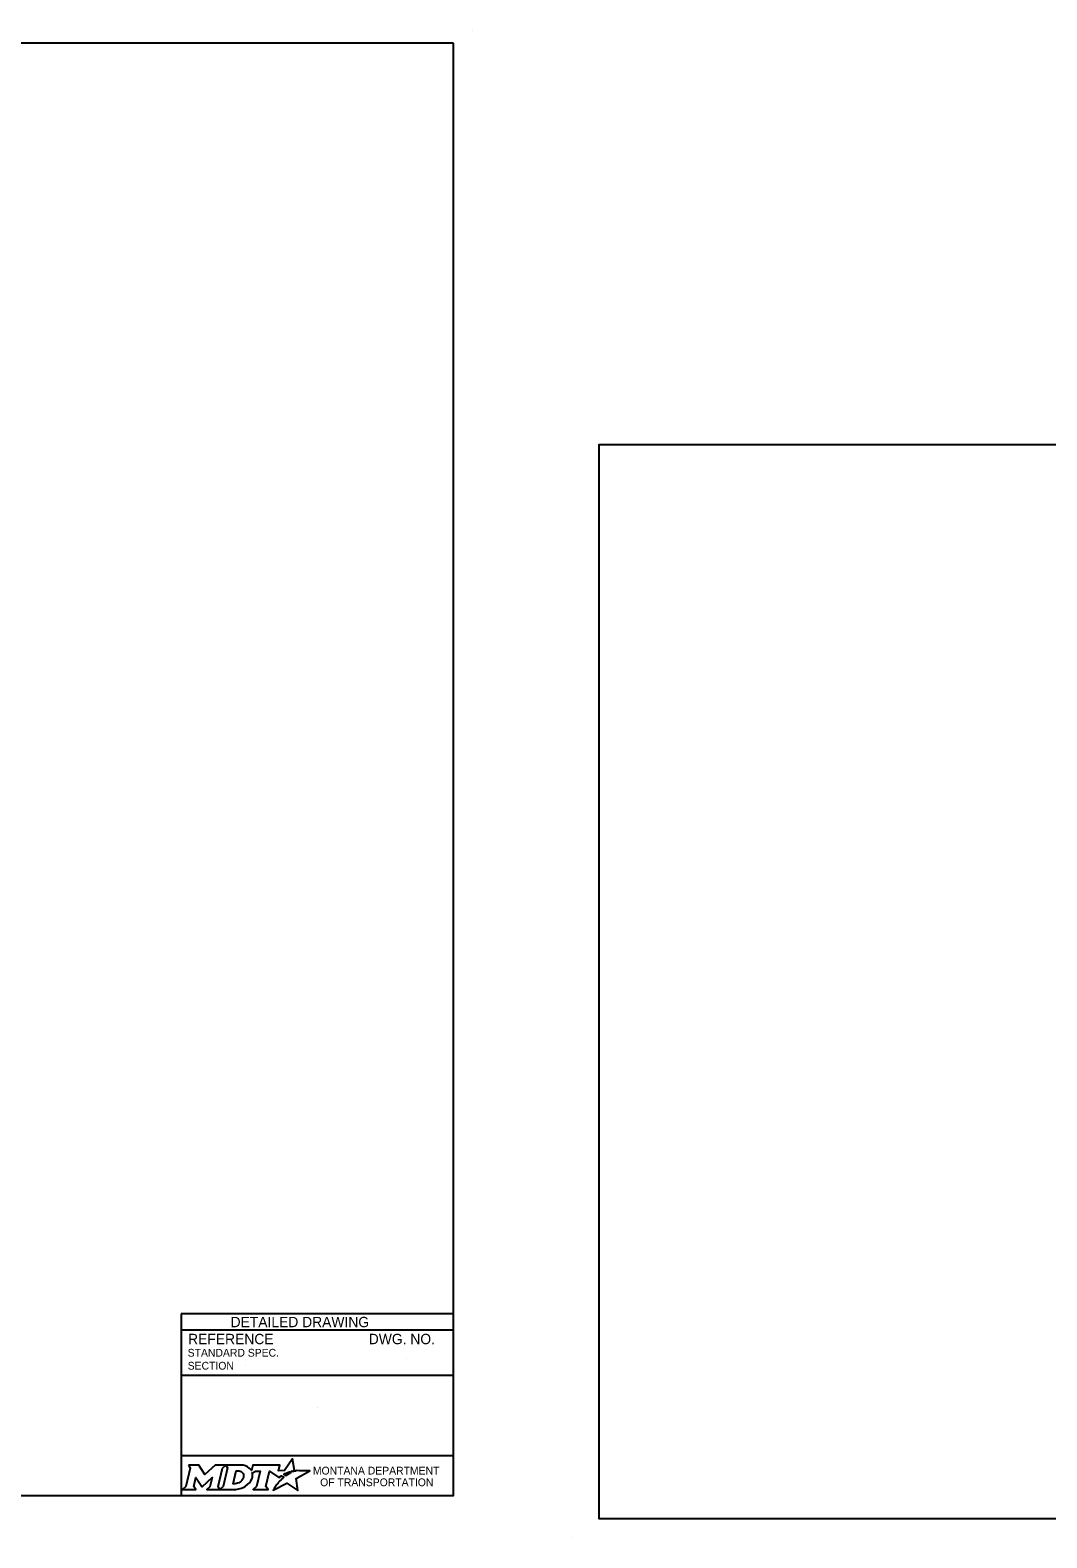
# Model space of a CAD drawing. Extents: x 49991.4 to 50061.4, y 49960.6 to 50011.4.
# Drawn here: x 50005.35 to 50013.19, y 49999.74 to 50011.36 of the extents above; entities that cross this region are included whole.
import ezdxf

# ---------------------------------------------------------------- set-up
doc = ezdxf.new("R2010")
doc.units = 0
doc.layers.add('Level 1', color=7, linetype='Continuous')
doc.layers.add('Level 2', color=7, linetype='Continuous')

msp = doc.modelspace()

# ---------------------------------------------------------------- linework, layer by layer
at = {"layer": 'Level 1'}
for p, q in [((50008.765, 50011.363), (50008.765, 50011.363)), ((50009.537, 49999.736), (50009.537, 49999.736))]:
    msp.add_line(p, q, dxfattribs=at)
for points in [[(50008.615, 50011.263), (50000.336, 50011.263), (50000.336, 50000.062), (50008.615, 50000.062)], [(50020.938, 50008.165), (50009.737, 50008.165), (50009.737, 49999.886), (50020.938, 49999.886)]]:
    msp.add_lwpolyline(points, close=True, dxfattribs=at)
at = {"layer": 'Level 2'}
for p, q in [((50008.615, 50001.462), (50006.515, 50001.462)), ((50006.515, 50001.462), (50006.515, 50000.062)), ((50008.615, 50001.337), (50006.515, 50001.337)), ((50007.009, 50001.063), (50007.009, 50001.063)), ((50008.251, 50001.122), (50008.251, 50001.122)), ((50008.615, 50000.987), (50006.515, 50000.987)), ((50007.565, 50000.738), (50007.565, 50000.738)), ((50008.615, 50000.369), (50006.515, 50000.369))]:
    msp.add_line(p, q, dxfattribs=at)
for points in [[(50007.377, 50000.245), (50007.367, 50000.25), (50007.378, 50000.253), (50007.39, 50000.255), (50007.373, 50000.345), (50007.313, 50000.254), (50007.266, 50000.253), (50007.276, 50000.297), (50007.067, 50000.297), (50007.057, 50000.255), (50007.051, 50000.263)], [(50006.57, 50000.297), (50006.584, 50000.274), (50006.551, 50000.131), (50006.525, 50000.108), (50006.627, 50000.108), (50006.613, 50000.131), (50006.629, 50000.201), (50006.673, 50000.132), (50006.678, 50000.132), (50006.753, 50000.202), (50006.737, 50000.13), (50006.712, 50000.108), (50006.814, 50000.108), (50006.8, 50000.132), (50006.833, 50000.274)], [(50006.833, 50000.274), (50006.859, 50000.297), (50006.776, 50000.297), (50006.697, 50000.224), (50006.652, 50000.297), (50006.57, 50000.297)], [(50006.972, 50000.297), (50006.859, 50000.297), (50006.873, 50000.275), (50006.839, 50000.131), (50006.814, 50000.108), (50006.925, 50000.108)], [(50006.996, 50000.211), (50006.995, 50000.203), (50006.992, 50000.193), (50006.988, 50000.185), (50006.982, 50000.178), (50006.976, 50000.171), (50006.968, 50000.164), (50006.959, 50000.16), (50006.95, 50000.156), (50006.941, 50000.154), (50006.932, 50000.153), (50006.916, 50000.153), (50006.94, 50000.253), (50006.956, 50000.253), (50006.963, 50000.252), (50006.971, 50000.25), (50006.977, 50000.247), (50006.983, 50000.243), (50006.988, 50000.238), (50006.992, 50000.232), (50006.995, 50000.226), (50006.996, 50000.218), (50006.996, 50000.215), (50006.996, 50000.211)], [(50007.064, 50000.238), (50007.088, 50000.251), (50007.125, 50000.251), (50007.097, 50000.131), (50007.069, 50000.108), (50007.185, 50000.108), (50007.168, 50000.131), (50007.196, 50000.251), (50007.268, 50000.2), (50007.289, 50000.215), (50007.309, 50000.204)], [(50007.253, 50000.148), (50007.237, 50000.124), (50007.233, 50000.116), (50007.227, 50000.107), (50007.225, 50000.103), (50007.33, 50000.156), (50007.414, 50000.101), (50007.401, 50000.194), (50007.508, 50000.252), (50007.458, 50000.253), (50007.428, 50000.253), (50007.407, 50000.254), (50007.401, 50000.252), (50007.396, 50000.251), (50007.387, 50000.249), (50007.377, 50000.245)], [(50007.327, 50000.217), (50007.324, 50000.215), (50007.306, 50000.225), (50007.316, 50000.231), (50007.32, 50000.233), (50007.329, 50000.237), (50007.335, 50000.239), (50007.343, 50000.243), (50007.35, 50000.245), (50007.362, 50000.238), (50007.358, 50000.236), (50007.353, 50000.233), (50007.349, 50000.231), (50007.344, 50000.228), (50007.342, 50000.227), (50007.339, 50000.225), (50007.337, 50000.224), (50007.334, 50000.222), (50007.332, 50000.221), (50007.329, 50000.219), (50007.327, 50000.217)], [(50006.97, 50000.116), (50006.979, 50000.118), (50006.992, 50000.124), (50007.012, 50000.135)], [(50007.267, 50000.164), (50007.267, 50000.164)]]:
    msp.add_lwpolyline(points, dxfattribs=at)
for centre, radius, start, end in [((50006.995, 50000.219), 0.0709, 339.5329, 15.8582), ((50006.951, 50000.236), 0.118, 300.9103, 339.1383)]:
    msp.add_arc(centre, radius, start, end, dxfattribs=at)
for centre, major_axis, ratio, start_param, end_param in [((50006.97, 50000.25), (0.0834, -0.0037), 0.568097, 0.61298, 1.570796), ((50007.026, 50000.257), (0.0361, -0.0295), 0.469099, 1.225588, 1.570796), ((50006.925, 50000.257), (0, 0.148), 0.987302, 3.139398, 3.456847), ((50007.26, 50000.156), (-0.00694, -0.00806), 0.008222, 0, 3.137361), ((50007.276, 50000.174), (-0.0098, -0.0102), 0.016458, 3.141593, 6.279097), ((50007.297, 50000.194), (-0.0112, -0.0097), 0.021651, 3.157348, 6.283185)]:
    msp.add_ellipse(centre, major_axis=major_axis, ratio=ratio, start_param=start_param, end_param=end_param, dxfattribs=at)

# ---------------------------------------------------------------- texts
for s, height, p in [('DETAILED DRAWING', 0.0799, (50006.896, 50001.36)), ('REFERENCE', 0.08, (50006.568, 50001.229)), ('DWG. NO.', 0.08, (50007.962, 50001.229)), ('STANDARD SPEC.', 0.06, (50006.565, 50001.133)), ('SECTION', 0.06, (50006.565, 50001.033)), ('MONTANA DEPARTMENT', 0.06, (50007.531, 50000.224)), ('OF TRANSPORTATION', 0.06, (50007.587, 50000.134))]:
    msp.add_text(s, height=height, dxfattribs=at).set_placement(p)

doc.saveas('drawing.dxf')
